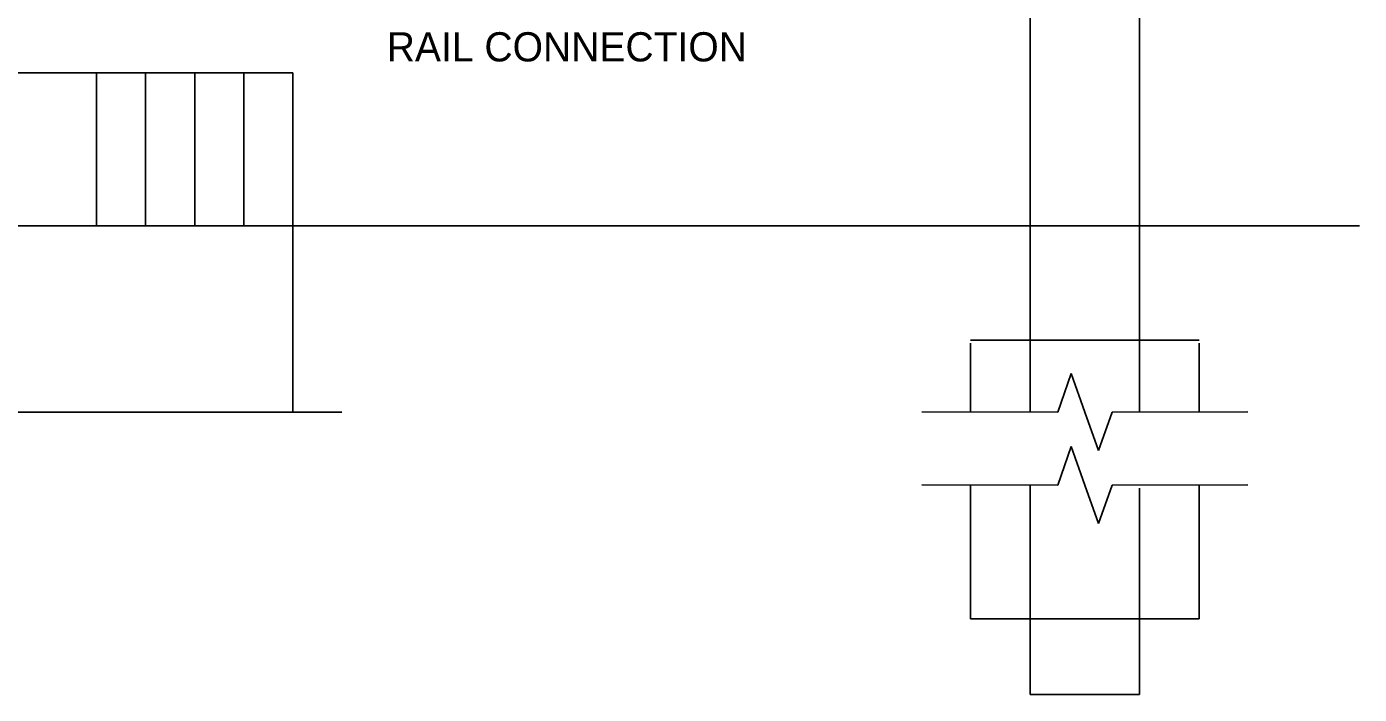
# Model space of a CAD drawing. Extents: x 49991.4 to 50021, y 49987.6 to 50011.4.
# Drawn here: x 50006.762 to 50009.5, y 49991.593 to 49992.964 of the extents above; entities that cross this region are included whole.
import ezdxf

# ---------------------------------------------------------------- set-up
doc = ezdxf.new("R2010")
doc.units = 0
for name, color, linetype in [('Level 1', 7, 'Continuous'), ('Level 2', 7, 'Continuous'), ('Level 4', 7, 'Continuous'), ('Level 6', 7, 'Continuous')]:
    doc.layers.add(name, color=color, linetype=linetype)

msp = doc.modelspace()

# ---------------------------------------------------------------- linework, layer by layer
at = {"layer": 'Level 1'}
for p, q in [((50008.8232, 49992.5551), (50008.8232, 49993.2246)), ((50009.0478, 49992.5551), (50009.0478, 49993.2246)), ((50007.3088, 49992.8695), (50005.3415, 49992.8695)), ((50006.9048, 49992.5551), (50006.9048, 49992.8695)), ((50007.0058, 49992.5551), (50007.0058, 49992.8695)), ((50007.1068, 49992.5551), (50007.1068, 49992.8695)), ((50007.2078, 49992.5551), (50007.2078, 49992.8695)), ((50007.3088, 49992.5551), (50007.3088, 49992.8695)), ((50007.0092, 49992.5549), (50005.3414, 49992.5549)), ((50007.0093, 49992.5551), (50009.4996, 49992.5551))]:
    msp.add_line(p, q, dxfattribs=at)
at = {"layer": 'Level 4'}
for p, q in [((50007.3088, 49992.1726), (50007.3088, 49992.5551)), ((50008.8232, 49992.5551), (50008.8232, 49992.1732)), ((50009.0478, 49992.5551), (50009.0478, 49992.1732)), ((50008.8233, 49992.3202), (50008.7005, 49992.3202)), ((50008.7005, 49992.1732), (50008.7005, 49992.3145)), ((50008.8233, 49992.3202), (50009.0477, 49992.3202)), ((50009.1707, 49992.3202), (50009.0477, 49992.3202)), ((50009.1707, 49992.1732), (50009.1707, 49992.3145)), ((50008.7004, 49991.7483), (50008.7004, 49992.0232)), ((50008.8234, 49991.5929), (50008.8234, 49992.0232)), ((50009.0478, 49991.5929), (50009.0478, 49992.0161)), ((50009.1708, 49991.7483), (50009.1708, 49992.0232)), ((50008.7004, 49991.7483), (50009.1708, 49991.7483)), ((50008.8234, 49991.5929), (50009.0478, 49991.5929))]:
    msp.add_line(p, q, dxfattribs=at)
at = {"layer": 'Level 6'}
for p, q in [((50008.9078, 49992.2519), (50008.8799, 49992.1728)), ((50008.9078, 49992.2519), (50008.9356, 49992.1728)), ((50006.3922, 49992.1726), (50007.4088, 49992.1726)), ((50008.6005, 49992.1734), (50008.88, 49992.1728)), ((50008.9356, 49992.1728), (50008.9639, 49992.0938)), ((50008.9918, 49992.1728), (50008.9639, 49992.0938)), ((50008.9918, 49992.1727), (50009.2707, 49992.1734)), ((50008.9078, 49992.1019), (50008.8799, 49992.0228)), ((50008.9078, 49992.1019), (50008.9356, 49992.0228)), ((50008.6004, 49992.0234), (50008.88, 49992.0228)), ((50008.9356, 49992.0228), (50008.9639, 49991.9438)), ((50008.9918, 49992.0228), (50008.9639, 49991.9438)), ((50008.9918, 49992.0228), (50009.2708, 49992.0234))]:
    msp.add_line(p, q, dxfattribs=at)

# ---------------------------------------------------------------- texts
at = {"layer": 'Level 2'}
msp.add_text('RAIL CONNECTION', height=0.06, dxfattribs=at).set_placement((50007.5014, 49992.8929))

doc.saveas('drawing.dxf')
